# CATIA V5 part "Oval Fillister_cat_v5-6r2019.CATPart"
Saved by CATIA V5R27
Part number: Oval Fillister
Bounding box of the stored display mesh (mm): x -5 to 5, y -4.99 to 4.99, z -7 to 4
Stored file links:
  E:\_Deepak\2017_Deepak\CATIA\Resources\Tutorial Files\Tutorials\c16_catia_v5_6r2016_tut\Bench vice\Oval Fillister_cat_v5-6r2016.CATPart
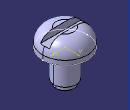
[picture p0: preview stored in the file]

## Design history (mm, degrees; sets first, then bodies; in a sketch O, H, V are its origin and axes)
Body1 (main body)
  Sketch1 on xy-plane, origin (0, 0, 0), H (1, 0, 0), V (0, 1, 0)
    circle A1 centre (0, 0) radius 5
    radius A1 = 5
  Pad1: profile Sketch1, direction (0, 0, 1), length 4
  Sketch2 on face of Pad1, origin (0, 0, 0), H (1, 0, 0), V (0, -1, 0)
    circle A1 centre (0, 0) radius 2.5
    radius A1 = 2.5
  Pad2: profile Sketch2, direction (0, 0, -1), length 6
  Sketch3 on face of Pad2, origin (0, 0, -6), H (1, 0, 0), V (0, -1, 0)
    circle A1 centre (0, 0) radius 2
    radius A1 = 2
  Pad3: profile Sketch3, direction (0, 0, -1), length 1
  Fillet1: radius 3, on 1 edge
  Sketch4 on yz-plane, origin (0, 0, 0), H (0, 1, 0), V (0, 0, 1)
    line L1 (-1, 4.5549) -> (1, 4.5549)
    line L2 (1, 4.5549) -> (1, 2.5)
    line L3 (1, 2.5) -> (-1, 2.5)
    line L4 (-1, 2.5) -> (-1, 4.5549)
    distance H L3 = 2.5
    distance L2 V = 1
    length L1 = 2
    horizontal: L1 H, L3 H
    vertical: L2 V, L4 V
  Pocket1: profile Sketch4, direction (-1, 0, 0), length 8, mirrored extent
